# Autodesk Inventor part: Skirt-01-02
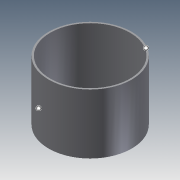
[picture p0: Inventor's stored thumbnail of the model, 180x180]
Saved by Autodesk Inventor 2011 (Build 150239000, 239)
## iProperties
Created: 2010-06
Part Number: Skirt-01-02
Document SubType Name: Modeling
Designer: mklassen
Density: 1 g/cm^3
OD: 36.000 in
THK: 0.625 in
LEN: 3.000 ft
SKVOFS: 6.000 in
Author: mklassen
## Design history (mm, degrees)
sketch "skSkirt"
  geometry: C1 r 473.075 at (0, 0); C2 r 457.2 at (0, 0); 1 further point
  constraints: 2 centre point, 1 coincident
  dimensions: "d0" = 914.4 diameter of C2 (derived); "d1" = 15.875 radial gap between concentric circles of C1 C2 (derived)
extrude "Extrusion1" new body sketch "skSkirt" stored distance "d2" = 914.4 (derived); taper "d3" = 0 deg
body "Solid1"
other parameters: "d4" = 152.4 (derived), "d5" = 0
